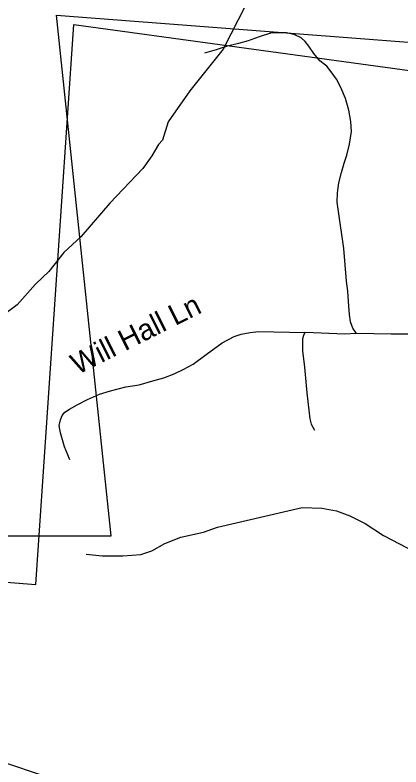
# Model space of a CAD drawing. Extents: x 1268485 to 1426702, y 514839 to 616766.
# Drawn here: x 1312893 to 1314099, y 535863 to 538210 of the extents above; entities that cross this region are included whole.
import ezdxf

# ---------------------------------------------------------------- set-up
doc = ezdxf.new("R2010")
doc.units = 0
for name, color, linetype in [('Old_Level_10', 7, 'Continuous'), ('Old_Level_32', 7, 'Continuous'), ('Old_Level_35', 7, 'Continuous'), ('Old_Level_48', 7, 'Continuous'), ('Old_Level_49', 7, 'Continuous'), ('Old_Level_53', 7, 'Continuous'), ('Old_Level_59', 7, 'Continuous'), ('Old_Level_62', 7, 'Continuous')]:
    doc.layers.add(name, color=color, linetype=linetype)

msp = doc.modelspace()

# ---------------------------------------------------------------- linework, layer by layer
at = {"layer": 'Old_Level_32'}
msp.add_lwpolyline([(1314926.29, 535195.055), (1314287.483, 535388.349), (1313303.169, 535727.341), (1312534.743, 535983.323), (1312206.986, 536082.965), (1311948.71, 536165), (1311692.53, 536248.106)], dxfattribs=at)
at = {"layer": 'Old_Level_35'}
for points in [[(1313928.639, 537378.919), (1313920.129, 537480.625), (1313903.213, 537597.145), (1313899.009, 537625.699), (1313900.137, 537655.38), (1313904.238, 537686.087), (1313912.748, 537717.87), (1313921.257, 537747.5), (1313929.767, 537772.927), (1313938.276, 537806.811), (1313943.505, 537845.976), (1313942.378, 537877.759), (1313936.123, 537912.772), (1313925.461, 537949.835), (1313910.594, 537983.669), (1313896.856, 538010.12), (1313880.964, 538032.368), (1313867.226, 538050.362), (1313844.978, 538067.382), (1313825.908, 538089.578), (1313811.144, 538112.851), (1313799.456, 538127.667), (1313786.743, 538138.33), (1313766.648, 538147.813), (1313741.221, 538154.169), (1313715.795, 538154.169), (1313691.394, 538153.144), (1313655.407, 538141.508), (1313621.471, 538129.82), (1313590.713, 538121.361), (1313552.676, 538111.826), (1313520.893, 538101.266), (1313484.906, 538090.603)], [(1313959.294, 537215.493), (1313947.709, 537232.82), (1313941.352, 537251.889), (1313938.276, 537275.163), (1313936.123, 537301.615), (1313932.843, 537348.264), (1313928.639, 537378.919)], [(1313064.55, 536821.895), (1313058.09, 536836.71), (1313047.53, 536862.136), (1313034.714, 536905.556), (1313030.511, 536928.83), (1313034.714, 536945.798), (1313040.148, 536959.588), (1313048.658, 536970.148), (1313063.422, 536979.683), (1313086.798, 536993.421), (1313119.504, 537009.313), (1313156.618, 537026.23), (1313191.477, 537036.892), (1313239.254, 537049.554), (1313280.469, 537055.962), (1313323.838, 537067.548), (1313357.877, 537077.133), (1313390.582, 537089.796), (1313418.162, 537103.585), (1313448.92, 537120.554), (1313490.238, 537150.184), (1313539.963, 537186.17), (1313576.975, 537206.316), (1313599.223, 537213.75), (1313627.828, 537218.979), (1313653.254, 537222.208), (1313798.636, 537218.517)], [(1313798.636, 537218.517), (1313794.125, 537209.494), (1313791.049, 537198.883), (1313791.049, 537161.82), (1313797.406, 537111.019), (1313804.788, 537030.484), (1313814.22, 536948.925), (1313818.526, 536933.084), (1313827.958, 536914.014)], [(1313959.294, 537215.493), (1313923.103, 537214.211), (1313799.251, 537218.517), (1313798.636, 537218.517)], [(1314199.103, 537213.647), (1314176.855, 537213.135), (1314135.229, 537213.39), (1314067.459, 537213.39), (1313959.294, 537215.493)]]:
    msp.add_lwpolyline(points, dxfattribs=at)
at = {"layer": 'Old_Level_48'}
msp.add_lwpolyline([(1309967.341, 536669.026), (1312958.395, 536431.996), (1313076.853, 538180.098), (1314535.142, 537980.379), (1314353.171, 536723.924), (1314745.846, 536446.652), (1314972.174, 536698.656), (1315031.403, 537054.201), (1315366.473, 537457.741), (1315917.719, 536862.159), (1316161.782, 536694.277), (1316644.398, 537079.676), (1316846.177, 536906.019), (1317046.346, 536359.734), (1317762.093, 535871.837), (1317992.842, 539661.54), (1319058.96, 539661.54), (1319058.96, 543276.26)], dxfattribs=at)
at = {"layer": 'Old_Level_49'}
msp.add_lwpolyline([(1309967.341, 536669.026), (1312958.395, 536431.996), (1313076.853, 538180.098), (1314535.142, 537980.379), (1314353.171, 536723.924), (1314745.846, 536446.652), (1314972.174, 536698.656), (1315031.403, 537054.201), (1315366.473, 537457.741), (1315917.719, 536862.159), (1316161.782, 536694.277), (1316644.398, 537079.676), (1316846.177, 536906.019), (1317046.346, 536359.734), (1317762.093, 535871.837), (1317992.842, 539661.54), (1319058.96, 539661.54), (1319058.96, 543276.26)], dxfattribs=at)
at = {"layer": 'Old_Level_53'}
msp.add_lwpolyline([(1309813.459, 536583.868), (1313193.163, 536583.868), (1313022.039, 538209.922), (1314690.5, 538081.55), (1314690.5, 536755.032), (1315075.53, 536755.032), (1315203.873, 537482.477), (1316102.275, 537225.731), (1316957.896, 537097.359), (1317214.582, 536498.286), (1317685.174, 536241.541), (1317984.641, 539493.649), (1318797.482, 539664.813), (1318968.606, 543126.623)], dxfattribs=at)
at = {"layer": 'Old_Level_59'}
msp.add_lwpolyline([(1313766.955, 538373.729), (1313740.504, 538357.018), (1313714.462, 538353.48), (1313679.808, 538326.26), (1313644.847, 538285.095), (1313613.782, 538241.419), (1313542.628, 538103.368), (1313439.487, 537973.313), (1313371.102, 537877.042), (1313353.878, 537819.114), (1313341.472, 537805.428), (1313320.66, 537770.517), (1313291.747, 537730.891), (1313189.221, 537623.034), (1313098.588, 537517.329), (1313045.582, 537468.322), (1312998.113, 537409.369), (1312957.205, 537369.999), (1312899.688, 537305.511), (1312850.68, 537268.755)], dxfattribs=at)
at = {"layer": 'Old_Level_62'}
msp.add_lwpolyline([(1313115.608, 536526.518), (1313165.538, 536521.391), (1313229.616, 536521.75), (1313285.698, 536526.363), (1313320.044, 536537.18), (1313360.542, 536560.146), (1313411.088, 536579.626), (1313481.42, 536595.466), (1313525.917, 536610.999), (1313789.409, 536672.976), (1313851.437, 536670.874), (1313897.164, 536661.75), (1313938.892, 536646.986), (1313986.361, 536622.225), (1314043.468, 536584.958), (1314142.303, 536534.566), (1314207.51, 536493.043), (1314254.672, 536455.98), (1314278.253, 536435.013), (1314301.321, 536400.872), (1314322.031, 536343.867), (1314339.256, 536309.88), (1314374.217, 536263.179)], dxfattribs=at)

# ---------------------------------------------------------------- texts
at = {"layer": 'Old_Level_10'}
msp.add_text('Will Hall Ln', height=65.61666, rotation=26.568236, dxfattribs=at).set_placement((1313088.168, 537086.198))

doc.saveas('drawing.dxf')
